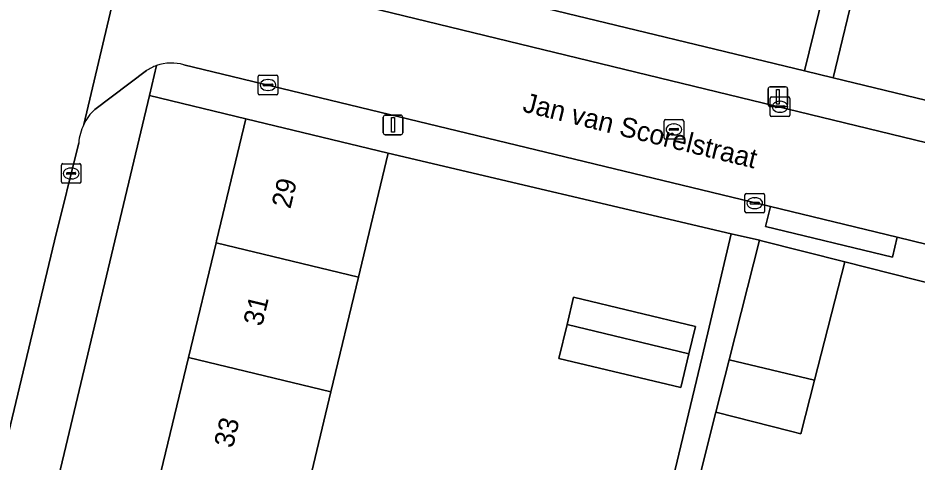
# Model space of a CAD drawing. Extents: x 162803 to 163818, y 381639 to 382475.
# Drawn here: x 163203.73 to 163249.5, y 382238.73 to 382261.36 of the extents above; entities that cross this region are included whole.
import ezdxf

# ---------------------------------------------------------------- set-up
doc = ezdxf.new("R2010")
doc.units = 0
for name, color, linetype in [('IMGEO_Erf', 7, 'Continuous'), ('IMGEO_Kolk', 7, 'Continuous'), ('IMGEO_Lichtmast', 7, 'Continuous'), ('IMGEO_Openbare_ruimte_label', 7, 'Continuous'), ('IMGEO_Pand', 7, 'Continuous'), ('IMGEO_Pand_nummerreeks', 7, 'Continuous'), ('IMGEO_Rijbaan_lokaal_open', 7, 'Continuous'), ('IMGEO_Rioolput', 7, 'Continuous'), ('IMGEO_Voetpad_open', 7, 'Continuous')]:
    doc.layers.add(name, color=color, linetype=linetype)

msp = doc.modelspace()

# ---------------------------------------------------------------- linework, layer by layer
at = {"layer": 'IMGEO_Erf'}
for points in [[(163203.591, 382207.345), (163205.056, 382213.443), (163206.52, 382219.533), (163208.007, 382225.721), (163209.412, 382231.567), (163210.888, 382237.709), (163212.412, 382244.052), (163213.817, 382249.895), (163213.842, 382250), (163215.335, 382256.213), (163210.426, 382257.404), (163208.662, 382250), (163195.885, 382196.387)], [(163236.101, 382233.806), (163238.571, 382244.081), (163240.049, 382250.363), (163222.583, 382254.463), (163221.512, 382250), (163221.068, 382248.151), (163219.666, 382242.308), (163218.144, 382235.965)], [(163255.26, 382246.533), (163245.824, 382248.922), (163244.291, 382242.9), (163243.596, 382240.169), (163243.067, 382240.303), (163239.254, 382241.272), (163237.689, 382234.97)]]:
    msp.add_lwpolyline(points, dxfattribs=at)
msp.add_lwpolyline([(163231.273, 382244.008), (163231.688, 382245.735), (163232.022, 382247.122), (163238.221, 382245.632), (163237.887, 382244.245), (163237.472, 382242.518)], close=True, dxfattribs=at)
at = {"layer": 'IMGEO_Kolk'}
for p, q in [((163215.962, 382257.514), (163215.962, 382258.366)), ((163216.037, 382258.44), (163216.889, 382258.44)), ((163216.963, 382258.366), (163216.963, 382257.514)), ((163216.221, 382257.934), (163216.221, 382257.946)), ((163216.659, 382257.897), (163216.261, 382257.897)), ((163216.264, 382257.983), (163216.662, 382257.983)), ((163216.45, 382258.22), (163216.475, 382258.22)), ((163216.705, 382257.946), (163216.705, 382257.934)), ((163216.889, 382257.44), (163216.037, 382257.44)), ((163216.473, 382257.66), (163216.448, 382257.66)), ((163242.028, 382256.403), (163242.028, 382257.255)), ((163242.103, 382257.329), (163242.955, 382257.329)), ((163242.516, 382257.109), (163242.541, 382257.109)), ((163243.029, 382257.255), (163243.029, 382256.403)), ((163242.287, 382256.823), (163242.287, 382256.835)), ((163242.725, 382256.786), (163242.327, 382256.786)), ((163242.33, 382256.872), (163242.728, 382256.872)), ((163242.539, 382256.549), (163242.514, 382256.549)), ((163242.771, 382256.835), (163242.771, 382256.823)), ((163242.955, 382256.329), (163242.103, 382256.329)), ((163205.94, 382253.004), (163205.94, 382253.856)), ((163206.015, 382253.93), (163206.867, 382253.93)), ((163206.428, 382253.71), (163206.453, 382253.71)), ((163206.941, 382253.856), (163206.941, 382253.004)), ((163206.199, 382253.424), (163206.199, 382253.436)), ((163206.637, 382253.387), (163206.239, 382253.387)), ((163206.242, 382253.473), (163206.64, 382253.473)), ((163206.683, 382253.436), (163206.683, 382253.424)), ((163206.867, 382252.93), (163206.015, 382252.93)), ((163206.451, 382253.15), (163206.426, 382253.15)), ((163240.741, 382251.491), (163240.741, 382252.343)), ((163240.816, 382252.417), (163241.668, 382252.417)), ((163241.742, 382252.343), (163241.742, 382251.491)), ((163241, 382251.911), (163241, 382251.923)), ((163241.438, 382251.874), (163241.04, 382251.874)), ((163241.043, 382251.96), (163241.441, 382251.96)), ((163241.229, 382252.197), (163241.254, 382252.197)), ((163241.484, 382251.923), (163241.484, 382251.911)), ((163241.668, 382251.417), (163240.816, 382251.417)), ((163241.252, 382251.637), (163241.227, 382251.637))]:
    msp.add_line(p, q, dxfattribs=at)
for points in [[(163215.962, 382257.514), (163215.962, 382258.366)], [(163216.037, 382258.44), (163216.889, 382258.44)], [(163216.963, 382258.366), (163216.963, 382257.514)], [(163216.889, 382257.44), (163216.037, 382257.44)], [(163242.028, 382256.403), (163242.028, 382257.255)], [(163242.103, 382257.329), (163242.955, 382257.329)], [(163243.029, 382257.255), (163243.029, 382256.403)], [(163242.955, 382256.329), (163242.103, 382256.329)], [(163205.94, 382253.004), (163205.94, 382253.856)], [(163206.015, 382253.93), (163206.867, 382253.93)], [(163206.941, 382253.856), (163206.941, 382253.004)], [(163206.867, 382252.93), (163206.015, 382252.93)], [(163240.741, 382251.491), (163240.741, 382252.343)], [(163240.816, 382252.417), (163241.668, 382252.417)], [(163241.742, 382252.343), (163241.742, 382251.491)], [(163241.668, 382251.417), (163240.816, 382251.417)]]:
    msp.add_lwpolyline(points, dxfattribs=at)
for centre, radius, start, end in [((163216.039, 382258.364), 0.0765, 91.552, 178.448), ((163216.039, 382258.364), 0.0765, 91.552, 178.448), ((163216.887, 382258.364), 0.0765, 1.552, 88.448), ((163216.887, 382258.364), 0.0765, 1.552, 88.448), ((163216.261, 382257.943), 0.0403, 85.8775, 175.7526), ((163216.258, 382257.933), 0.0366, 178.938, 274.7102), ((163216.662, 382257.94), 0.043, 264.8664, 352.4533), ((163216.666, 382257.945), 0.0386, 1.7309, 96.639), ((163216.039, 382257.516), 0.0765, 181.552, 268.448), ((163216.039, 382257.516), 0.0765, 181.552, 268.448), ((163216.887, 382257.516), 0.0765, 271.552, 358.448), ((163216.887, 382257.516), 0.0765, 271.552, 358.448), ((163242.105, 382257.253), 0.0765, 91.552, 178.448), ((163242.105, 382257.253), 0.0765, 91.552, 178.448), ((163242.953, 382257.253), 0.0765, 1.552, 88.448), ((163242.953, 382257.253), 0.0765, 1.552, 88.448), ((163242.327, 382256.832), 0.0403, 85.8775, 175.7526), ((163242.324, 382256.822), 0.0366, 178.938, 274.7102), ((163242.728, 382256.829), 0.043, 264.8664, 352.4533), ((163242.732, 382256.834), 0.0386, 1.7309, 96.639), ((163242.105, 382256.405), 0.0765, 181.552, 268.448), ((163242.105, 382256.405), 0.0765, 181.552, 268.448), ((163242.953, 382256.405), 0.0765, 271.552, 358.448), ((163242.953, 382256.405), 0.0765, 271.552, 358.448), ((163206.017, 382253.854), 0.0765, 91.552, 178.448), ((163206.017, 382253.854), 0.0765, 91.552, 178.448), ((163206.865, 382253.854), 0.0765, 1.552, 88.448), ((163206.865, 382253.854), 0.0765, 1.552, 88.448), ((163206.239, 382253.433), 0.0403, 85.8775, 175.7526), ((163206.236, 382253.423), 0.0366, 178.938, 274.7102), ((163206.64, 382253.43), 0.043, 264.8664, 352.4533), ((163206.644, 382253.435), 0.0386, 1.7309, 96.639), ((163206.017, 382253.006), 0.0765, 181.552, 268.448), ((163206.017, 382253.006), 0.0765, 181.552, 268.448), ((163206.865, 382253.006), 0.0765, 271.552, 358.448), ((163206.865, 382253.006), 0.0765, 271.552, 358.448), ((163240.818, 382252.341), 0.0765, 91.552, 178.448), ((163240.818, 382252.341), 0.0765, 91.552, 178.448), ((163241.666, 382252.341), 0.0765, 1.552, 88.448), ((163241.666, 382252.341), 0.0765, 1.552, 88.448), ((163241.04, 382251.92), 0.0403, 85.8775, 175.7526), ((163241.037, 382251.91), 0.0366, 178.938, 274.7102), ((163241.441, 382251.917), 0.043, 264.8664, 352.4533), ((163241.445, 382251.922), 0.0386, 1.7309, 96.639), ((163240.818, 382251.493), 0.0765, 181.552, 268.448), ((163240.818, 382251.493), 0.0765, 181.552, 268.448), ((163241.666, 382251.493), 0.0765, 271.552, 358.448), ((163241.666, 382251.493), 0.0765, 271.552, 358.448)]:
    msp.add_arc(centre, radius, start, end, dxfattribs=at)
for centre, major_axis, ratio, start_param, end_param in [((163216.449, 382257.94), (-0.387, 0.002), 0.722429, 4.712389, 7.853982), ((163216.474, 382257.94), (-0.39, 0.002), 0.717154, 1.570796, 4.712389), ((163242.515, 382256.829), (-0.387, 0.002), 0.722429, 4.712389, 7.853982), ((163242.54, 382256.829), (-0.39, 0.002), 0.717154, 1.570796, 4.712389), ((163206.427, 382253.43), (-0.387, 0.002), 0.722429, 4.712389, 7.853982), ((163206.452, 382253.43), (-0.39, 0.002), 0.717154, 1.570796, 4.712389), ((163241.228, 382251.917), (-0.387, 0.002), 0.722429, 4.712389, 7.853982), ((163241.253, 382251.917), (-0.39, 0.002), 0.717154, 1.570796, 4.712389)]:
    msp.add_ellipse(centre, major_axis=major_axis, ratio=ratio, start_param=start_param, end_param=end_param, dxfattribs=at)
at = {"layer": 'IMGEO_Lichtmast'}
for p, q in [((163242.024, 382257.842), (163242.814, 382257.842)), ((163242.814, 382257.842), (163242.024, 382257.842)), ((163241.924, 382256.942), (163241.924, 382257.742)), ((163241.924, 382257.742), (163241.924, 382256.942)), ((163242.914, 382257.742), (163242.914, 382256.942)), ((163242.914, 382256.942), (163242.914, 382257.742)), ((163242.814, 382256.842), (163242.024, 382256.842)), ((163242.024, 382256.842), (163242.814, 382256.842)), ((163222.328, 382255.503), (163222.328, 382256.303)), ((163222.328, 382256.303), (163222.328, 382255.503)), ((163222.428, 382256.403), (163223.218, 382256.403)), ((163223.218, 382256.403), (163222.428, 382256.403)), ((163223.318, 382256.303), (163223.318, 382255.503)), ((163223.318, 382255.503), (163223.318, 382256.303)), ((163223.218, 382255.403), (163222.428, 382255.403)), ((163222.428, 382255.403), (163223.218, 382255.403))]:
    msp.add_line(p, q, dxfattribs=at)
for points in [[(163242.344, 382257.717), (163242.494, 382257.717), (163242.494, 382256.967), (163242.344, 382256.967), (163242.344, 382257.717)], [(163222.748, 382256.278), (163222.898, 382256.278), (163222.898, 382255.528), (163222.748, 382255.528), (163222.748, 382256.278)]]:
    msp.add_lwpolyline(points, dxfattribs=at)
for centre, start, end in [((163242.024, 382257.742), 90, 180), ((163242.024, 382257.742), 90, 180), ((163242.814, 382257.742), 0, 90), ((163242.814, 382257.742), 360, 90), ((163242.024, 382256.942), 180, 270), ((163242.024, 382256.942), 180, 270), ((163242.814, 382256.942), 270, 0), ((163242.814, 382256.942), 270, 0), ((163222.428, 382256.303), 90, 180), ((163222.428, 382256.303), 90, 180), ((163223.218, 382256.303), 0, 90), ((163223.218, 382256.303), 360, 90), ((163222.428, 382255.503), 180, 270), ((163222.428, 382255.503), 180, 270), ((163223.218, 382255.503), 270, 0), ((163223.218, 382255.503), 270, 0)]:
    msp.add_arc(centre, 0.1, start, end, dxfattribs=at)
at = {"layer": 'IMGEO_Pand'}
for points in [[(163244.992, 382263.659), (163231.804, 382266.82), (163231.34, 382266.931), (163230.143, 382261.953), (163243.783, 382258.657)], [(163259.071, 382260.284), (163258.585, 382260.401), (163246.436, 382263.313), (163245.227, 382258.308), (163257.862, 382255.255)], [(163221.068, 382248.151), (163221.512, 382250), (163222.583, 382254.463), (163215.335, 382256.213), (163213.842, 382250), (163213.817, 382249.895)], [(163212.412, 382244.052), (163219.666, 382242.308), (163221.068, 382248.151), (163213.817, 382249.895)], [(163239.932, 382243.934), (163244.291, 382242.9), (163245.824, 382248.922), (163241.588, 382250), (163241.482, 382250.027)], [(163237.887, 382244.245), (163238.221, 382245.632), (163232.022, 382247.122), (163231.688, 382245.735)], [(163237.887, 382244.245), (163231.688, 382245.735), (163231.273, 382244.008), (163237.472, 382242.518)], [(163212.412, 382244.052), (163210.888, 382237.709), (163218.144, 382235.965), (163219.666, 382242.308)], [(163239.932, 382243.934), (163239.254, 382241.272), (163243.067, 382240.303), (163243.596, 382240.169), (163244.291, 382242.9)]]:
    msp.add_lwpolyline(points, close=True, dxfattribs=at)
at = {"layer": 'IMGEO_Rijbaan_lokaal_open'}
for points in [[(163207.079, 382255.92), (163210.146, 382268.873), (163213.29, 382280.995), (163205.323, 382282.906), (163197.427, 382250), (163190.618, 382221.745), (163198.38, 382219.883), (163205.6, 382250), (163206.824, 382254.998)], [(163211.791, 382264.994), (163210.396, 382267.272), (163210.146, 382268.873), (163207.079, 382255.92)], [(163212.184, 382258.973), (163242.04, 382251.745), (163248.5, 382250.182), (163249.251, 382250), (163266.425, 382245.801), (163267.529, 382245.521), (163268.607, 382250), (163268.719, 382250.464), (163267.687, 382250.701), (163214.495, 382263.638)], [(163207.644, 382256.692), (163210.284, 382258.675)]]:
    msp.add_lwpolyline(points, dxfattribs=at)
for centre, radius, start, end in [((163211.57, 382256.738), 2.325, 109.6329, 123.5879), ((163211.557, 382256.752), 2.308, 74.2458, 109.4495), ((163209.442, 382254.784), 2.622, 133.289, 154.3128), ((163209.483, 382254.759), 2.67, 154.2189, 174.8611)]:
    msp.add_arc(centre, radius, start, end, dxfattribs=at)
at = {"layer": 'IMGEO_Rioolput'}
for p, q in [((163236.625, 382255.247), (163236.625, 382256.099)), ((163236.7, 382256.173), (163237.552, 382256.173)), ((163237.626, 382256.099), (163237.626, 382255.247)), ((163236.884, 382255.667), (163236.884, 382255.679)), ((163237.322, 382255.63), (163236.924, 382255.63)), ((163236.927, 382255.716), (163237.325, 382255.716)), ((163237.113, 382255.953), (163237.138, 382255.953)), ((163237.368, 382255.679), (163237.368, 382255.667)), ((163237.552, 382255.173), (163236.7, 382255.173)), ((163237.136, 382255.393), (163237.111, 382255.393))]:
    msp.add_line(p, q, dxfattribs=at)
for points in [[(163236.625, 382255.247), (163236.625, 382256.099)], [(163236.7, 382256.173), (163237.552, 382256.173)], [(163237.626, 382256.099), (163237.626, 382255.247)], [(163237.552, 382255.173), (163236.7, 382255.173)]]:
    msp.add_lwpolyline(points, dxfattribs=at)
for centre, radius, start, end in [((163236.702, 382256.097), 0.0765, 91.552, 178.448), ((163236.702, 382256.097), 0.0765, 91.552, 178.448), ((163237.55, 382256.097), 0.0765, 1.552, 88.448), ((163237.55, 382256.097), 0.0765, 1.552, 88.448), ((163236.924, 382255.676), 0.0403, 85.8775, 175.7526), ((163236.921, 382255.666), 0.0366, 178.938, 274.7102), ((163237.325, 382255.673), 0.043, 264.8664, 352.4533), ((163237.329, 382255.678), 0.0386, 1.7309, 96.639), ((163236.702, 382255.249), 0.0765, 181.552, 268.448), ((163236.702, 382255.249), 0.0765, 181.552, 268.448), ((163237.55, 382255.249), 0.0765, 271.552, 358.448), ((163237.55, 382255.249), 0.0765, 271.552, 358.448)]:
    msp.add_arc(centre, radius, start, end, dxfattribs=at)
for centre, major_axis, ratio, start_param, end_param in [((163237.112, 382255.673), (-0.387, 0.002), 0.722429, 4.712389, 7.853982), ((163237.137, 382255.673), (-0.39, 0.002), 0.717154, 1.570796, 4.712389)]:
    msp.add_ellipse(centre, major_axis=major_axis, ratio=ratio, start_param=start_param, end_param=end_param, dxfattribs=at)
at = {"layer": 'IMGEO_Voetpad_open'}
for points in [[(163244.773, 382300.239), (163243.29, 382294.095), (163241.986, 382288.7), (163240.502, 382282.557), (163239.204, 382277.182), (163237.725, 382271.058), (163237.103, 382268.482), (163232.434, 382269.446), (163231.804, 382266.82), (163244.992, 382263.659), (163243.783, 382258.657), (163245.227, 382258.308), (163246.436, 382263.313), (163258.585, 382260.401)], [(163245.227, 382258.308), (163243.783, 382258.657), (163230.143, 382261.953), (163226.243, 382262.852), (163218.465, 382264.714), (163214.952, 382265.544), (163214.495, 382263.638), (163267.687, 382250.701), (163268.719, 382250.464), (163269.549, 382250.274)], [(163208.662, 382250), (163210.426, 382257.404), (163210.789, 382258.928)], [(163210.789, 382258.928), (163210.426, 382257.404), (163215.335, 382256.213), (163222.583, 382254.463), (163240.049, 382250.363), (163241.482, 382250.027), (163241.588, 382250), (163245.824, 382248.922), (163255.26, 382246.533), (163265.32, 382244.147), (163269.065, 382243.217), (163269.474, 382244.937)], [(163249.251, 382250), (163248.5, 382250.182), (163248.255, 382249.171), (163241.795, 382250.734), (163242.04, 382251.745), (163212.184, 382258.973)], [(163210.284, 382258.675), (163207.644, 382256.692)], [(163271.062, 382250.149), (163271.528, 382251.889), (163269.342, 382252.458), (163261.691, 382254.301), (163257.862, 382255.255), (163245.227, 382258.308)], [(163206.824, 382254.998), (163205.6, 382250), (163198.38, 382219.883), (163197.737, 382217.199), (163182.664, 382154.325), (163181.993, 382151.527), (163172.306, 382111.79)], [(163174.255, 382106.523), (163174.616, 382107.997), (163176.66, 382116.978), (163193.704, 382187.277), (163194.519, 382190.638), (163195.134, 382193.161), (163195.885, 382196.387), (163208.662, 382250)], [(163268.286, 382245.329), (163267.529, 382245.521), (163266.425, 382245.801), (163249.251, 382250)]]:
    msp.add_lwpolyline(points, dxfattribs=at)
for points in [[(163242.04, 382251.745), (163241.795, 382250.734), (163248.255, 382249.171), (163248.5, 382250.182)], [(163239.254, 382241.272), (163239.932, 382243.934), (163241.482, 382250.027), (163240.049, 382250.363), (163238.571, 382244.081), (163236.101, 382233.806), (163234.992, 382229.253), (163235.378, 382229.161), (163234.566, 382225.779), (163234.169, 382225.874), (163234.11, 382225.631), (163233.649, 382223.738), (163234.006, 382223.651), (163235.152, 382223.372), (163236.743, 382229.908), (163237.178, 382232.235), (163237.689, 382234.97)]]:
    msp.add_lwpolyline(points, close=True, dxfattribs=at)
for centre, radius, start, end in [((163211.57, 382256.738), 2.325, 109.6329, 123.5879), ((163211.557, 382256.752), 2.308, 74.2458, 109.4495), ((163209.442, 382254.784), 2.622, 133.289, 154.3128), ((163209.483, 382254.759), 2.67, 154.2189, 174.8611)]:
    msp.add_arc(centre, radius, start, end, dxfattribs=at)

# ---------------------------------------------------------------- texts
at = {"layer": 'IMGEO_Openbare_ruimte_label'}
msp.add_text('Jan van Scorelstraat', height=1, rotation=346.1722, dxfattribs=at).set_placement((163229.377, 382256.593))
at = {"layer": 'IMGEO_Pand_nummerreeks'}
for s, p in [('29', (163217.598, 382251.594)), ('31', (163216.158, 382245.606)), ('33', (163214.667, 382239.399))]:
    msp.add_text(s, height=1, rotation=76.4865, dxfattribs=at).set_placement(p)

doc.saveas('drawing.dxf')
